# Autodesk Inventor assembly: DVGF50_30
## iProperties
Created: 2010-04
Part Number: DVGF50_30
Document SubType Name: Assembly
Designer: TB
Mass: 764.494 g
Surface Area: 1410.45 cm^2
Volume: 764.494 cm^3
Density: 1 g/cm^3
Description: KM DVGF 50/30 - 100 mm
Slaglengde: 100.000 mm
Author: TB
